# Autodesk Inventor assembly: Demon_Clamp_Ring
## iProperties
Shininess: 64.0
Length Units: 11269
Angle Units: 11279
Time Units: 11290
Mass Units: 11283
Length Display Precision: 3
Angle Display Precision: 2
Compacted: True
Created: 2005-04
Part Number: Demon_Clamp_Ring
Document SubType Name: Assembly
Designer: John Blackburn
Manufacturer: Standard
Standards Organization: Custom
Density: 0.0
Volumn: 0.0
Area: 0.0
PropertySet Name: Model Information
Control State: 0
Master: False
Checked Out: False
Author: John Blackburn
